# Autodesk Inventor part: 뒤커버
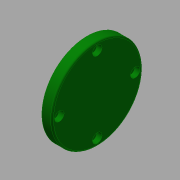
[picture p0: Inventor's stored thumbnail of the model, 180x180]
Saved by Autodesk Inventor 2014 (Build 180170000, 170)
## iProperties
Created: 2015-09
Part Number: 뒤커버
Material: 알루미늄 6061
Document SubType Name: Modeling
Designer: mduedu
Density: 2.71 g/cm^3
Mass: 54.0417 g
Surface Area: 84.9688 cm^2
Volume: 19.9416 cm^3
Appearance: Dark Green
Author: mduedu
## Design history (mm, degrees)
sketch "스케치1"
  geometry: L1 (-15.5, 47)-(-15.5, 78); L2 (-15.5, 78)-(-22.5, 78); L3 (-22.5, 78)-(-22.5, 67); L4 (-25.5, 67)-(-25.5, 47); L5 (-79.5, 39.5)-(-79.5, 54.5) reference; L6 (48.5, 54.5)-(48.5, 39.5) reference; L7 (-79.5, 47)-(48.5, 47); L8 (-22.5, 67)-(-25.5, 67); L9 (-25.5, 47)-(-15.5, 47); 1 further point
  constraints: 14 end point, 4 midpoint, 3 parallel, 1 collinear, 1 point on line, 1 vertical
  dimensions: "d6" = 62 diameter of L2 L7; "d7" = 7 distance of L1.end L2.end; "d8" = 40 diameter of L3.end L7; "d32" = 10 distance between parallel lines of L1 L4
revolve "회전1" sketch "스케치1" stored, may be unused: angle "d4" = 90 deg
sketch "스케치4"
  geometry: C1 r 31 at (0, 0) reference; 2 further points
  constraints: 1 coincident
hole "구멍3" sketch "스케치4" at (0, 0) diameter "d33" = 33; stored, may be unused: countersink angle "d37" = 90 deg, drill point angle "d39" = 0 deg; dims "d34" = 6, "d35" = 4, "d36" = 2, "d38" = 5
fillet "모깎기4" dims "d40" = 1
chamfer "모따기2" distance "d41" = 1; stored, may be unused: second distance "d42" = 2, angle "d43" = 45 deg
sketch "스케치6" dims "d56" = 52
  geometry: C1 r 31 at (0, 0) reference; 5 further points
  constraints: 2 vertical alignment, 1 coincident, 7 other
  dimensions: "d59" = 360 deg dimension on C1.centre point (0, 26) (derived)
hole "구멍4" sketch "스케치6" at (0, 26), (-26, 0), (0, -26), (26, 0) diameter "d49" = 3.4; stored, may be unused: countersink angle "d53" = 90 deg, drill point angle "d55" = 0 deg; dims "d50" = 6, "d51" = 6.5, "d52" = 3.4, "d54" = 8
node "솔리드1"
node "참조1"
node "참조2"
